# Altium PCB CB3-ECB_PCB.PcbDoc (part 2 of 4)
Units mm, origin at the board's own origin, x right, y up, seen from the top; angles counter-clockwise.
Board outline 195 x 139 mm, 4 copper layers (Top Layer, Layer 1, Layer 2, Bottom Layer), stack 1.56 mm thick; 363 components, 264 nets, 1430 pads, 630 vias.
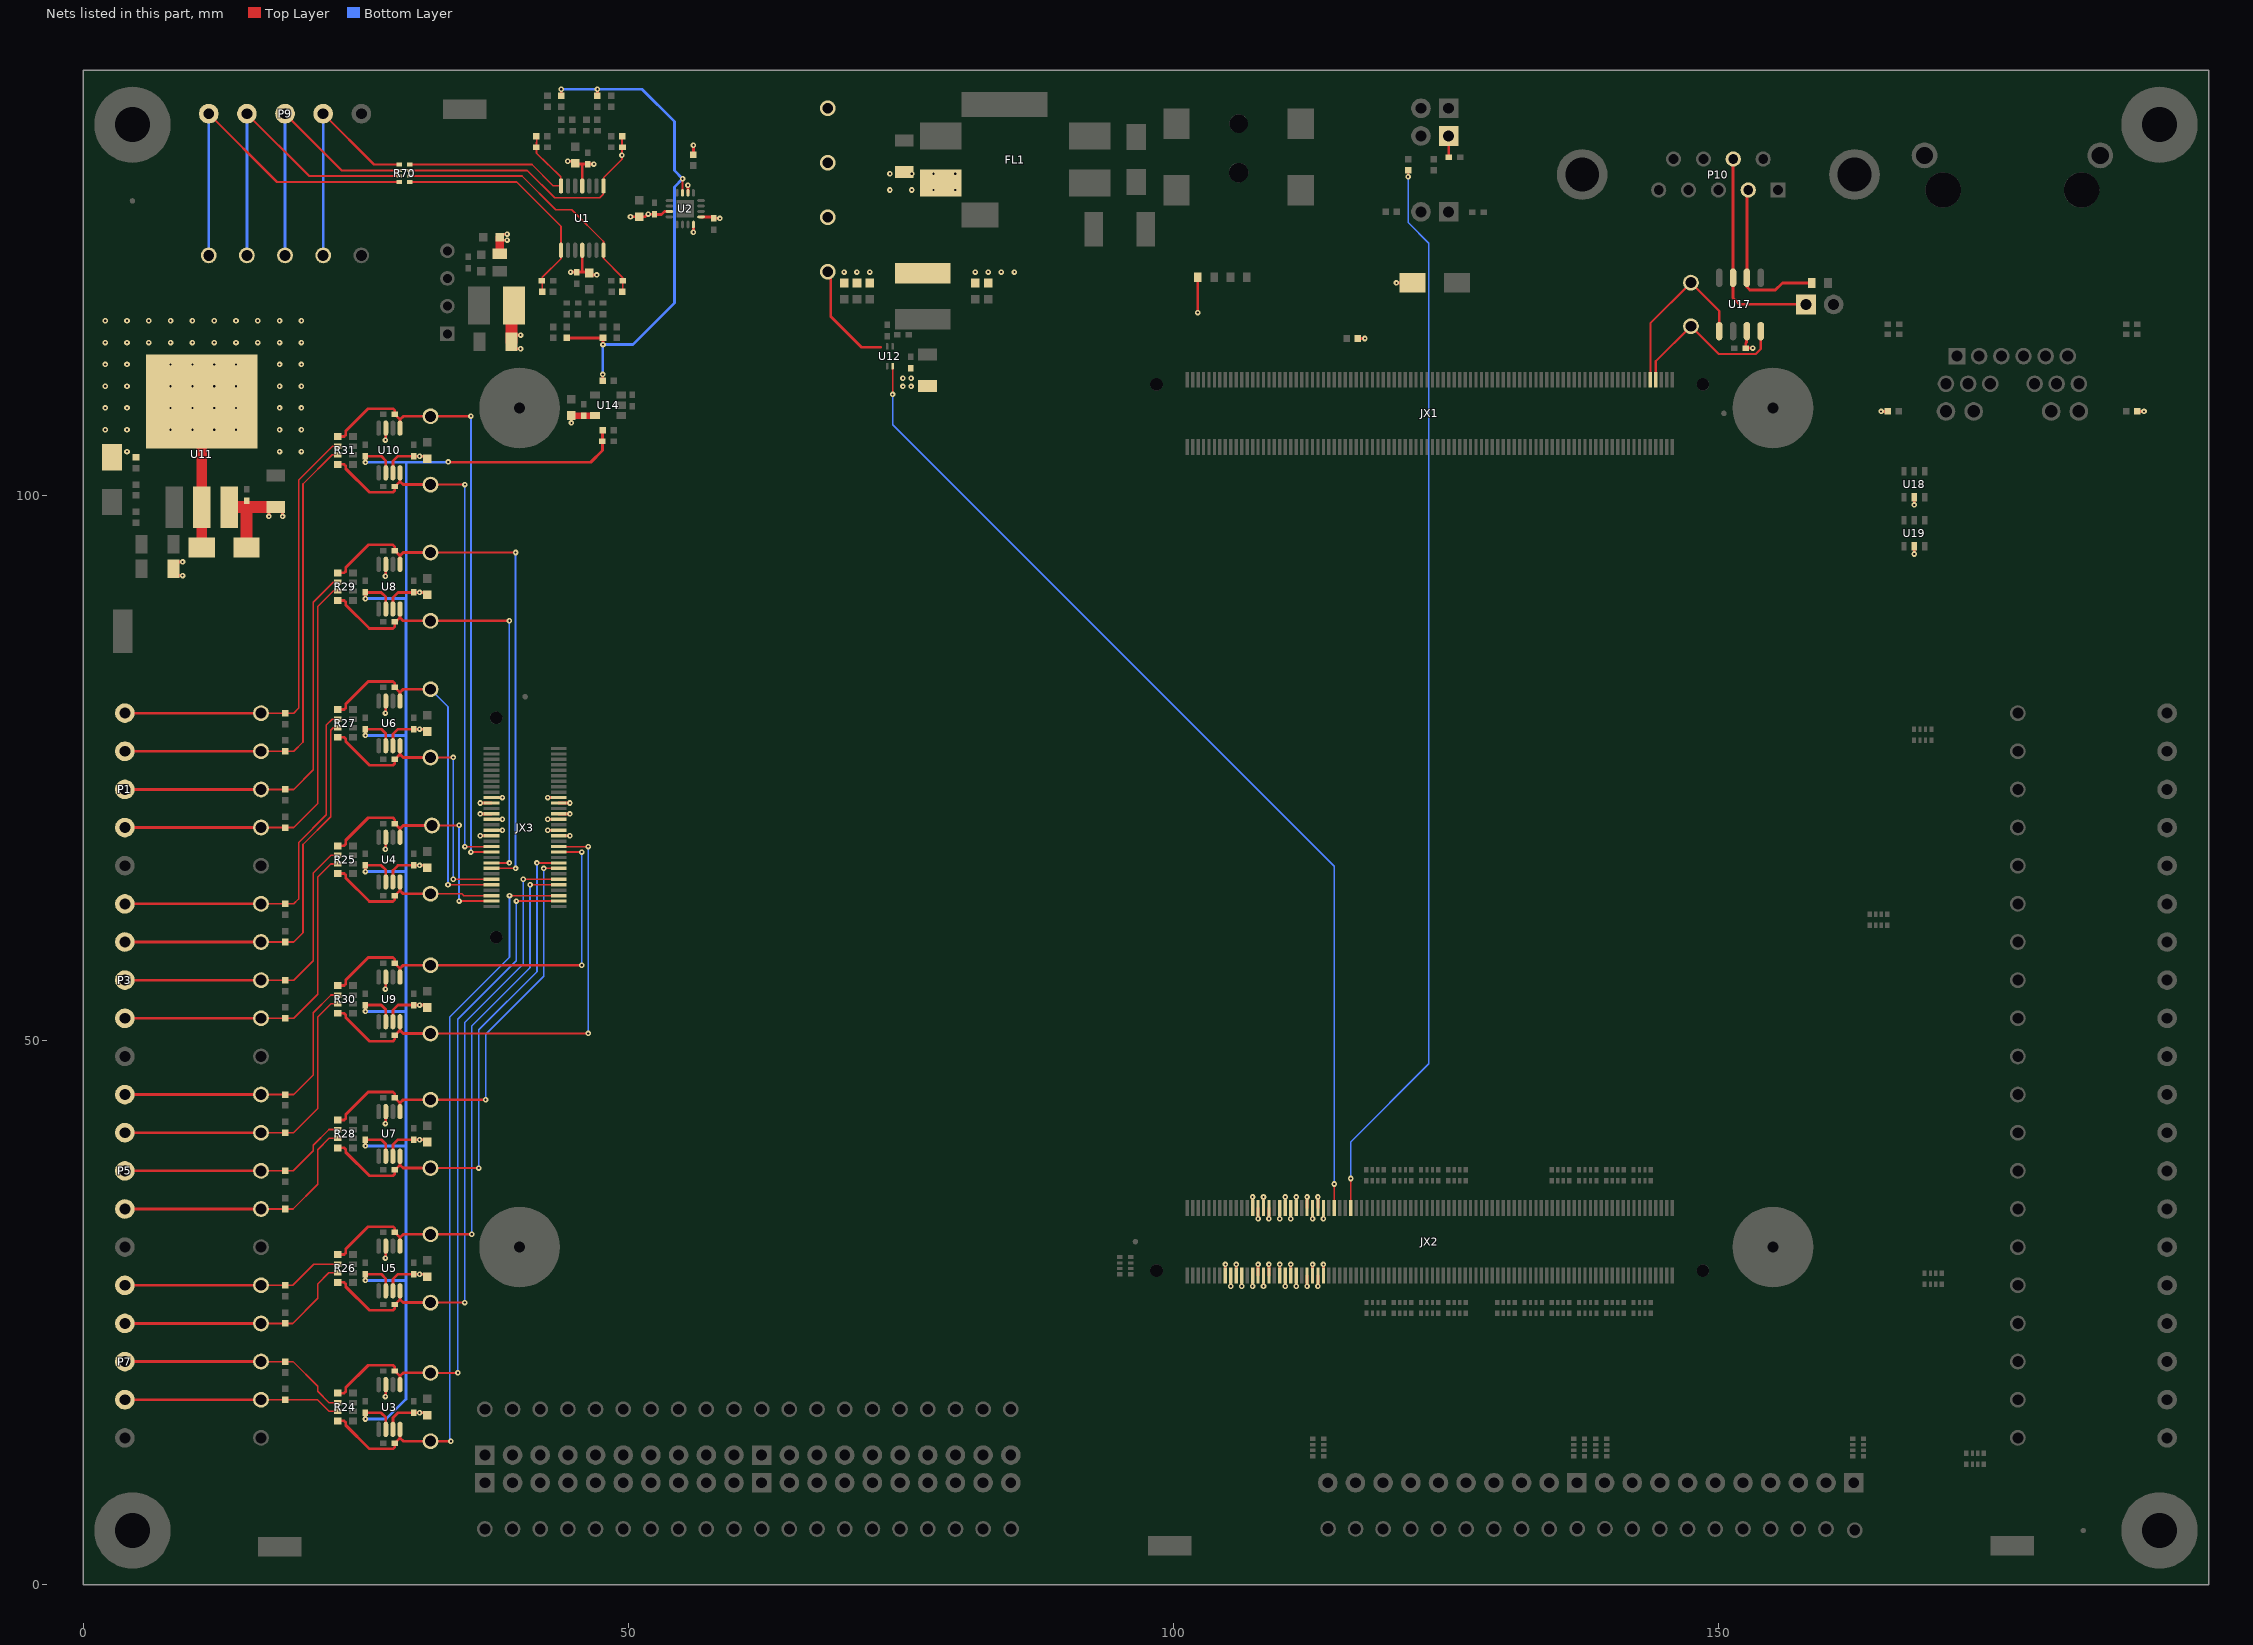
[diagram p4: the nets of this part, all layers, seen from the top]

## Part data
C1 C3 C9 C19 C22 C29 C32 C39 C42 C47 C52 C56 C64 C65 C69 C71 C79 C82 C83: library part CMP-055-000003-7, "CAP CER 10UF 10V X5R 0603 10% (Generic Imperix Component)", Case/Package=0603, Dielectric=X5R, Tolerance=10%, Voltage Rating (DC)=10V
C2 C4 C7 C8 C18 C21 C28 C31 C38 C41 C46 C51 C57 C58 C61 C67 C70 C73 C74 C75 C76 C77 C78 C84: library part CMP-004-000006-18, "CAP CER 100NF 25V X7R 0402 10% (Generic Imperix Component)", Case/Package=0402, Dielectric=X7R, Tolerance=10%, Voltage Rating (DC)=25V
C5 C10 C12 C14: library part CMP-027-000004-13, "CAP CER 56PF 50V C0G 0402 1% (Generic Imperix Component)", Case/Package=0402, Dielectric=C0G, Tolerance=1%, Voltage Rating (DC)=50V
C6 C11 C13 C15: library part CMP-012-000001-12, "CAP CER 10NF 25V X7R 0402 10% (Generic Imperix Component)", Case/Package=0402, Dielectric=X7R, Tolerance=10%, Voltage Rating (DC)=25V
C16 C17 C23 C24 C26 C27 C34 C35 C36 C37 C44 C45 C48 C49 C54 C55: library part CMP-004-000007-13, "CAP CER 12PF 50V C0G 0402 5% (Generic Imperix Component)", Case/Package=0402, Dielectric=C0G, Tolerance=5%, Voltage Rating (DC)=50V
C20 C25 C30 C33 C40 C43 C50 C53 C72 C80 C81: library part CMP-004-000008-13, "CAP CER 1UF 6.3V X5R 0402 5% (Generic Imperix Component)", Case/Package=0402, Dielectric=X5R, Tolerance=5%, Voltage Rating (DC)=6.3V
C59 C60 C62 C63 C66 C68: library part CMP-002-000022-5, "CAP CER 10UF 25V X5R 1206 10% (Generic Imperix Component)", Case/Package=1206, Dielectric=X5R, Tolerance=10%, Voltage Rating (DC)=25V
D1 D3 D4: library part CMP-005-000028-6, "Diode Schottky 40 V 3A Surface Mount SMA", Average Rectified Current=3A, Case/Package=DO-214AC, Forward Voltage=450mV, Max Forward Surge Current (Ifsm)=100A, Max Operating Temperature=150°C, Max Repetitive Reverse Voltage (Vrrm)=40V, Max Reverse Current=300uA, Min Operating Temperature=-55°C, Package Quantity=1
D2: library part CMP-030-000001-20, "32.5V Clamp 71A (8/20µs) Ipp Tvs Diode Surface Mount SMA (DO-214AC) Unidirectional", Breakdown Voltage=17.6V, Case/Package=DO-214AC, Clamping Voltage=32.5V, Leakage Current=200nA, Max Operating Temperature=150°C, Max Surge Current=1mA, Min Breakdown Voltage=16.7V, Min Operating Temperature=-55°C, Operating Supply Voltage=15V, Package Quantity=1, Peak Pulse Current=71A, Peak Pulse Power=400W, Power Line Protection=No
F1 F2 F3 F4 F5: library part CMP-031-000000-13, "Fiducial for pick&place (No BOM)"
F6: library part CMP-00170-3, "PTC Resettable Fuse 1.1A(hold)  1.95A(trip) 16VDC 1812", Case Code (Imperial)=1812, Case Code (Metric)=4532, Current Rating=100A, Hold Current=1.1A, Max Operating Temperature=85°C, Max Power Dissipation=800mW, Max Voltage Rating (DC)=16V, Min Operating Temperature=-40°C, Package Quantity=1500, Trip Current=1.95A
FL1: library part CMP-00068-6, "EMI Filter Block 15A 50VDC Flat Style SMD Automotive Embossed T/R"
J1 J2 J3 J4 J5: library part CMP-018-000000-12, "Natural PC Test Point Plating Surface Mount Mounting Type", Case/Package=1206, Color=Natural, Max Operating Temperature=125°C, Min Operating Temperature=-55°C, Package Quantity=2000
J6: library part CMP-056-000006-11, "2.0 x 6.5 mm, 5.0 A, Horizontal, Surface Mount (SMT), Dc Power Jack Connector", Body Color=Black, Flammability Rating="UL94 V-0", Max Operating Temperature=85°C, Min Operating Temperature=-25°C
JX1: library part CMP-070-000035-8, "JX1 for BBoard", Max Current Rating=1.25A, Max Operating Temperature=125°C, Max Voltage Rating (AC)=125V, Min Operating Temperature=-55°C
JX2: library part CMP-070-000034-11, "JX2 for BBoard", Max Current Rating=1.25A, Max Operating Temperature=125°C, Max Voltage Rating (AC)=125V, Min Operating Temperature=-55°C
JX3: library part CMP-070-000037-3, "JX3 for BBoard"
L1: library part CMP-259-000003-2, "Inductor Power Shielded Wirewound 3.3uH 30% 100KHz Ferrite 4.95A 0.0299Ohm DCR 2424 T/R", Case/Package=Nonstandard, Current Rating=4.95A, DC Resistance (DCR)=30mR, Inductance Tolerance=30%, Max Operating Temperature=105°C, Min Operating Temperature=-40°C, Saturation Current=6.5A, Test Frequency=100kHz
L3: library part CMP-007-000004-5, "Ferrite Beads Multi-Layer High Current 600Ohm 25% 100MHz 2A 100mOhm DCR 0805 T/R", Case Code (Imperial)=0805, Case Code (Metric)=2012, Current Rating=2A, DC Resistance (DCR)=100mR, Max Operating Temperature=125°C, Min Operating Temperature=-55°C, Package Quantity=4000, Self Resonant Frequency=100MHz, Tolerance=25%
L4: library part CMP-00092-4, "Inductor Power Wirewound 22uH 10% 0.6A 0.6Ohm DCR 1812", Case/Package=Nonstandard, DC Resistance (DCR)=600mR, Max DC Current=600mA, Max Operating Temperature=125°C, Min Operating Temperature=-40°C, Tolerance=10%
LED1: library part CMP-030-000000-10, "LED GREEN CLEAR 0603 SMD", Case Code (Imperial)=0603, Case Code (Metric)=1608, Color=Green, Forward Current=30mA, Forward Voltage=2.3V, Illumination Color=Green,Yellow, Lens Color=Colorless, Max Operating Temperature=85°C, Min Operating Temperature=-55°C, Package Quantity=3000, Power Dissipation=75mW, Reverse Voltage=5V, Test Current=5mA
P1 P2 P3 P4 P5 P6 P7 P8 P9: library part CMP-003-000046-13, "Conn PC Terminal Block 5 POS 3.5mm Solder Thru-Hole 17.5A", Color=Green, Current=10A, Current Rating=17.5A, Flammability Rating="UL94 V-0", Package Quantity=100, Voltage=300V, Voltage Rating=160V
P10: library part CMP-255-000000-9, "Conn D-Subminiature PIN 9 POS 2.74mm Solder RA Thru-Hole 9 Terminal 1 Port", Color=Black, Current Rating=5A, Manufacturer_Name="Amphenol Communications Solutions", Max Operating Temperature=105°C, Min Operating Temperature=-55°C, Voltage Rating=250V
P11 P14 P15 P16 P17 P18: library part CMP-003-000044-17, "Connector Header Through Hole 10 position 0.100\" (2.54mm)", Current Rating=3A, Flammability Rating="UL94 V-0", Insulation Color=Black, Max Operating Temperature=105°C, Min Operating Temperature=-40°C, Package Quantity=500, Voltage Rating=750V
P12 P13: library part CMP-003-000045-14, "Connector Header Through Hole 2 position 0.100\" (2.54mm)", Contact Resistance=25mR, Current=3A, Flammability Rating="UL94 V-0", Housing Color=Black, Insulation Resistance=10GR, Max Operating Temperature=105°C, Min Operating Temperature=-40°C, Package Quantity=1000, Voltage=50V, Voltage Rating (AC)=750V
P19: library part CMP-265-000000-4, "Conn Modular Jack RCP 12 POS 2.03mm Solder RA Thru-Hole 16 Terminal 1 Port Tray", Color=Green,Orange,Yellow, Max Operating Temperature=70°C, Min Operating Temperature=0°C
P20 P21: library part CMP-070-000025-6, "Connector Header Through Hole 2 position 0.100\" (2.54mm)", Contact Resistance=25mR, Current=3A, Flammability Rating="UL94 V-0", Housing Color=Black, Insulation Resistance=10GR, Max Operating Temperature=105°C, Min Operating Temperature=-40°C, Package Quantity=1000, Voltage=50V, Voltage Rating (AC)=750V
P22 P23 P24 P25: library part CMP-002-000068-13, "WA-SMSE SMT Steel Spacer, M3x5mm Thread External"
P26 P27 P28 P29: library part CMP-00128-10, "Hole and pad for spacer M3"
R2: library part CMP-00098-1, "RES SMD 1.8KΩ 1/8W 25PPM 0603 0.1% (Generic Imperix Component)", Case/Package=0603, Power Rating=1/8W, Temperature Coefficient=25ppm/°C, Tolerance=0.1%
R3 R4 R35 R37 R38 R39 R40 R71 R72 R73 R74 R75 R76 R77 R78 R79: library part CMP-00160-1, "RES SMD 1MΩ 1/16W 100PPM 0402 1% (Generic Imperix Component)", Case/Package=0402, Power Rating=1/16W, Temperature Coefficient=100ppm/°C, Tolerance=1%
R5 R8 R9 R11 R14 R16 R19 R20 R23 R41: library part CMP-009-000034-6, "RES SMD 6.19KΩ 1/16W 100PPM 0402 1% (Generic Imperix Component)", Case/Package=0402, Power Rating=1/16W, Temperature Coefficient=100ppm/°C, Tolerance=1%
R6 R7 R10 R12 R17 R18 R21 R22: library part CMP-00012-1, "RES SMD 3.09KΩ 1/16W 100PPM 0402 1% (Generic Imperix Component)", Case/Package=0402, Power Rating=1/16W, Temperature Coefficient=100ppm/°C, Tolerance=1%
R13 R15 R42 R46 R47 R48 R49 R50 R51 R52 R53 R58 R59 R60 R61 R62 R63 R64 R65 R70: library part CMP-009-000035-3, "Res Thick Film Array 33 Ohm 5% ±200ppm/°C ISOL 8-Pin 0804(4 X 0402) Convex SMD Automotive T/R", Case Code (Imperial)=0402, Case Code (Metric)=1005, Case/Package=0804, Max Operating Temperature=125°C, Min Operating Temperature=-55°C, Number of Resistors=4, Package Quantity=10000, Power Dissipation=63mW, Power Per Element=62.5mW, Resistance Tolerance=5%, Temperature Coefficient=200ppm/°C, Voltage Rating=50V, Voltage Rating (DC)=100V
R24 R25 R26 R27 R28 R29 R30 R31: library part CMP-017-000003-7, "10k Ohm ±0.1% 100mW Power Per Element Isolated 4 Resistor Network/Array ±25ppm/°C 1206 (3216 Metric), Convex, Long Side Terminals", Case Code (Imperial)=1206, Case Code (Metric)=3216, Max Operating Temperature=125°C, Min Operating Temperature=-55°C, Number of Resistors=4, Power Per Element=100mW, Temperature Coefficient=25ppm/°C, Tolerance=0.1%, Tolerance Relative=0.05%
R32 R82 R83: library part CMP-132-000003-2, "RES SMD 249Ω 1/16W 100PPM 0402 1% (Generic Imperix Component)", Case/Package=0402, Power Rating=1/16W, Temperature Coefficient=100ppm/°C, Tolerance=1%
R33 R84: library part CMP-150-000004-2, "RES SMD 777Ω 1/16W 25PPM 0402 0.1% (Generic Imperix Component)", Case/Package=0402, Power Rating=1/16W, Temperature Coefficient=25ppm/°C, Tolerance=0.1%
R34 R80: library part CMP-004-000018-3, "RES SMD 1.6Ω 1/16WW 200PPM 0402 5% (Generic Imperix Component)", Case/Package=0402, Power Rating=1/16W, Temperature Coefficient=200ppm/°C, Tolerance=5%
R36: library part CMP-006-000016-3, "RES SMD 120Ω 1/8W 50PPM 0603 1% (Generic Imperix Component)", Case/Package=0603, Power Rating=1/8W, Temperature Coefficient=50ppm/°C, Tolerance=1%
R43 R44: library part CMP-017-000008-4, "RES SMD 120Ω 1/16W 25PPM 0402 0.1% (Generic Imperix Component)", Case/Package=0402, Power Rating=1/16W, Temperature Coefficient=25ppm/°C, Tolerance=0.1%
R54 R55 R56 R57 R66 R67 R68 R69: library part CMP-062-000000-4, "Res Thick Film Array 10KΩ 5% ±200ppm/°C ISOL 8-Pin 0804(4 X 0402) Convex SMD Automotive T/R", Case Code (Imperial)=0402, Case Code (Metric)=1005, Case/Package=0804, Max Operating Temperature=125°C, Min Operating Temperature=-55°C, Number of Resistors=4, Package Quantity=1, Power Dissipation=63mW, Power Per Element=62.5mW, Resistance Tolerance=5%, Temperature Coefficient=200ppm/°C, Voltage Rating=50V, Voltage Rating (DC)=100V
R81: library part CMP-009-000006-6, "RES SMD 100KΩ 1/16W 100PPM 0402 1% (Generic Imperix Component)", Case/Package=0402, Power Rating=1/16W, Temperature Coefficient=100ppm/°C, Tolerance=1%
TP1 TP2 TP3 TP4 TP5 TP6 TP7 TP8 TP9 TP10 TP11 TP12 TP13 TP14 TP15 TP16 TP17 TP18 TP19 TP20 TP21 TP22 TP23 TP24 TP25 TP26 TP27 TP28 TP29 TP30 TP31 TP32 TP33 TP34 TP35 TP36 TP37 TP38 TP39 TP40 TP41 TP42 TP43 TP44 TP45 TP46 TP47 TP48 TP49 TP50 TP51 TP52 TP53 TP54 TP55 TP56 TP57 TP58 TP59 TP60 TP61 TP62 TP63 TP64 TP65 TP66 TP67 TP68 TP69 TP70 TP71 TP72 TP73 TP74 TP75 TP76 TP77 TP78 TP79 TP80 TP81 TP82 TP83 TP84 TP85 TP86 TP87 TP88 TP89 TP90 TP91 TP92 TP93 TP94 TP95 TP96 TP97 TP98 TP99 TP100 TP101 TP102 TP103 TP104 TP105 TP106 TP107 TP108 TP109 TP110 TP111 TP112 TP113 TP114 TP115 TP116 TP117 TP118 TP119 TP120 TP121 TP122 TP123 TP124 TP125 TP128 TP129: library part CMP-049-000000-14, "Black PC Test Point, Miniature Phosphor Bronze Silver Plating Through Hole Mounting Type", Color=Black, Package Quantity=100
U1: library part CMP-00166-1, "Precision Amplifiers Low-power low-noise four-channel precision amplifier with e-trim and super-beta inputs", Case/Package=TSSOP-14, Input Bias Current=100pA, Input Offset Voltage (Vos)=2uV, Max Operating Temperature=85°C, Min Operating Temperature=-40°C, Operating Supply Current=0.24mA
U2: library part CMP-029-000000-12, "DAC 4-CH Resistor-String 14-bit 16-Pin LFCSP EP T/R", Case/Package=QFN-16, Max Operating Temperature=105°C, Max Output Voltage=5.5V, Min Input Voltage=750mV, Min Operating Temperature=-40°C, Min Output Voltage=2.7V, Package Quantity=1500, Power Dissipation=7.15mW, Supply Current=1.1mA
U3 U4 U5 U6 U7 U8 U9 U10: library part CMP-011-000002-8, "Low Noise, Precision, 150MHz, Fully Differential Amplifier 8-TSOP -40 to 125", Case/Package=TSOP-8, Input Bias Current=1uA, Input Offset Voltage (Vos)=50uV, Max Operating Temperature=125°C, Min Operating Temperature=-40°C, Operating Supply Current=1.35mA
U11: library part CMP-011-000003-10, "IC REG LINEAR ADJ 1.5A DDPAK", Case/Package=TO263-3, Dropout Voltage=2V, Max Operating Temperature=125°C, Max Output current=1.5A, Max Output Voltage=37V, Max Supply Voltage=40V, Min Input Voltage=4.2V, Min Operating Temperature=0°C, Min Output Voltage=1.25V, Package Quantity=1, Power Supply Rejection Ratio (PSRR)=64dB, Quiescent Current=3.5mA, Reference Voltage=1.3V
U12: library part CMP-00162-5, "LMR436x0, 36-V, 1-A Buck Converter"
U13: library part CMP-004-000025-11, "Isolated Module DC DC Converter 1 Output 5V 200mA 10.8V - 13.2V Input", Isolation Voltage=1kV, Max Operating Temperature=85°C, Max Output current=200mA, Max Output Voltage=5V, Max Power Dissipation=1W, Max Supply Voltage=13.2V, Min Input Voltage=10.8V, Min Operating Temperature=-40°C
U14: library part CMP-00165-2, "Single Operational Amplifier, 50 µV Offset, 0.25 µV/°C, Zero-Drift Precision, Low Power", Case/Package=SOT-23-5, Input Bias Current=50pA, Input Offset Voltage (Vos)=14uV, Max Operating Temperature=125°C, Min Operating Temperature=-40°C, Operating Supply Current=21uA, Output Current per Channel=5mA
U17: library part CMP-00049-3, "Texas Instruments - SN65HVD232DR - Can Transceiver, 1MBPS, 1/1, 3.3V, SOIC-8, Full Reel", Case/Package=SOIC-8, Max Operating Temperature=85°C, Max Supply Voltage=3.6V, Min Operating Temperature=-40°C, Min Supply Voltage=3V, Package Quantity=2500, Supply Current=17mA
U18 U19: library part CMP-050-000000-12, "HDMIULC6 Series 4 Channel 6 V Bi-Directional ESD Protection - SOT-23-6", Breakdown Voltage=6V, Case/Package=SOT23-6, Clamping Voltage=17V, Leakage Current=500nA, Max Operating Temperature=125°C, Min Operating Temperature=-55°C, Operating Supply Voltage=5V, Package Quantity=1, Peak Pulse Current=5A, Power Line Protection=Yes, Test Current=1mA

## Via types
v1: diameter 0.508, hole 0.2, Top Layer to Bottom Layer, tented both sides, 435 vias
v2: diameter 0.508, hole 0.2, Top Layer to Bottom Layer, 194 vias
v3: diameter 0.66, hole 0.33, Top Layer to Bottom Layer, tented both sides, 1 vias

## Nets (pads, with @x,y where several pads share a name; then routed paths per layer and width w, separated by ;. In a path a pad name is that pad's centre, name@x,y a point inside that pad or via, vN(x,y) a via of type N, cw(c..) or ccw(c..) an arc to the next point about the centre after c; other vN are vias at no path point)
2V5REFBUF: C20.2 C25.2 C30.2 C33.2 C40.2 C43.2 C50.2 C53.2 C81.2 R80.2 U3.2 U4.2 U5.2 U6.2 U7.2 U8.2 U9.2 U10.2 | length 166.7
  Top Layer w0.254: v1(25.875,15.23) C20.2@25.875,15.806 27.324,15.806 27.747,15.383 U3.2@27.747,14.282 ; v1(25.875,27.943) C30.2@25.875,28.519 27.324,28.519 27.747,28.096 U5.2@27.747,26.994 ; v1(25.875,40.287) C40.2@25.875,40.864 27.324,40.863 27.747,40.44 U7.2@27.747,39.339 ; v1(25.875,52.632) C50.2@25.875,53.208 27.324,53.208 27.747,52.784 U9.2@27.747,51.683 ; v1(25.875,65.459) C25.2@25.875,66.035 27.324,66.035 27.747,65.611 U4.2@27.747,64.51 ; v1(25.875,77.956) C33.2@25.875,78.532 27.324,78.532 27.747,78.108 U6.2@27.747,77.007 ; v1(25.875,90.503) C43.2@25.875,91.079 27.324,91.079 27.747,90.656 U8.2@27.747,89.554 ; v1(25.875,103) C53.2@25.875,103.576 27.324,103.576 27.747,103.153 U10.2@27.747,102.051 ; v2(33.475,103.05) 33.5,103.025 46.55,103.025 47.625,104.1 C81.2@47.625,104.95 47.625,105.95 R80.2@47.65,105.975
  Bottom Layer w0.254: v1(25.875,15.23) 27.78,15.23 29.6,17.05 29.6,27.943 ; v1(25.875,27.943) 29.6,27.943 29.6,40.287 ; v1(25.875,40.287) 29.6,40.287 ; v1(25.875,52.632) 29.6,52.632 ; v1(25.875,65.459) 29.6,65.459 ; v1(25.875,77.956) 29.6,77.956 ; v1(25.875,103) 25.9,103.025 29.675,103.025 ; v1@25.9,90.528 29.625,90.528 ; v2(33.475,103.05) 33.45,103.025 29.675,103.025 ; 29.6,40.287 29.6,52.632 ; 29.6,52.632 29.6,65.459 ; 29.6,65.459 29.6,77.956 ; 29.6,77.956 29.6,90.503 29.625,90.528 ; 29.625,90.528 29.625,102.975 29.675,103.025
2V5REFOUT: R7.2 R12.2 R18.2 R22.2 R81.1 U2.15 | length 46.8
  Top Layer w0.152: U2.15@54.974,127.735 U2.15@54.972,127.734 54.972,129.035 v1(54.975,129.037)
  Top Layer w0.254: R22.2@43.852,136.633 v1(43.852,137.251) ; R7.2@44.366,114.432 R12.2@47.676,114.432 v1(47.676,113.814) ; R18.2@47.162,136.633 v1(47.162,137.251) ; R81.1@47.65,110.5 v1(47.65,111.075)
  Bottom Layer w0.254: v1(43.852,137.251) v1(47.162,137.251) 47.26,137.251 51.249,137.251 54.225,134.275 54.225,129.788 v1(54.975,129.037) 54.225,128.287 54.225,117.625 50.414,113.814 v1(47.676,113.814) 47.663,113.801 47.663,111.088 v1(47.65,111.075)
3V3: C7.2 C56.2 C69.2 C70.2 C71.2 C78.2 C82.2 C83.2 D4.K L1.2 P12.1 R11.2 R41.1 R82.2 R83.2 TP122.1 U2.8 U2.9 U2.14 U12.8 U17.3 U18.5 U19.5 | length 23.3
  Top Layer w0.25: v1(55.974,124.128) U2.8@55.974,124.832 ; U2.9@56.672,125.532 57.705,125.532 57.828,125.409 C7.2@57.828,125.396 57.83,125.398 58.398,125.398 v1(58.4,125.4) ; C70.2@152.525,113.5 v2(153.175,113.5) ; v2(164.95,107.68) R83.2@165.575,107.68 ; R82.2@188.525,107.68 v2(189.075,107.68) v2@189.125,107.68
  Top Layer w0.254: U2.14@55.471,127.736 v1(55.471,128.44) ; R11.2@55.972,131.5 v1(55.972,132.1) ; TP122.1@68.3,121.092 68.571,120.821 68.571,116.384 71.38,113.575 U12.8@73.087,113.575 73.142,113.575 ; R41.1@116.95,114.375 v1@117.583,114.375 ; v1(120.475,119.475) D4.K@121.95,119.475 ; P12.1@125.27,132.96 125.27,131.005 C78.2@125.275,131 ; C70.2@152.525,113.5 152.525,113.925 152.6,114 152.6,115.015 U17.3@152.635,115.05 ; v1(168,94.6) U19.5@168,95.3 ; v1(168,99.1) U18.5@168,99.8
  other v1: 117.586,114.375
  other v2: 69.8,120.475 70.975,120.475 72.15,120.475 81.825,120.475 83.025,120.475 84.225,120.475 85.425,120.475
5V2: C1.2 C2.2 C8.2 C9.2 C18.2 C19.2 C21.2 C22.2 C28.2 C29.2 C31.2 C32.2 C38.2 C39.2 C41.2 C42.2 C46.2 C47.2 C51.2 C52.2 C63.2 C77.2 C79.2 D1.A D3.K JX3.10 JX3.11 JX3.13 JX3.14 JX3.16 JX3.17 JX3.44 JX3.45 JX3.47 JX3.48 JX3.50 JX3.51 R32.2 TP123.1 U1.4 U2.3 U3.3 U3.7 U4.3 U4.7 U5.3 U5.7 U6.3 U6.7 U7.3 U7.7 U8.3 U8.7 U9.3 U9.7 U10.3 U10.7 U11.2 U14.5 | length 79
  Top Layer w0.25: C63.2@8.675,92.625 v2(9.1,92.625) ; C63.2@8.675,93.875 v2(9.1,93.875) ; v1(44.7,120.467) C2.2@45.272,120.467 ; v2(44.775,106.625) C79.2@44.775,107.3 ; C1.2@46.417,120.389 46.495,120.467 46.495,120.403 46.692,120.205 v1(47.1,120.205) ; v1(50.2,125.55) C9.2@51,125.55 51.52,125.55 51.759,125.789 v1(51.828,125.789) 51.835,125.782 52.393,125.782 C8.2@52.4,125.775 ; C8.2@52.4,125.8 C8.2@52.4,125.775 ; U2.3@53.772,126.034 53.324,126.034 53.04,125.75 52.425,125.75 C8.2@52.4,125.775
  Top Layer w0.254: v1@27.747,17.314 U3.7@27.747,18.381 ; v1@27.747,30.026 U5.7@27.747,31.094 ; v1@27.747,42.371 U7.7@27.747,43.439 ; v1@27.747,54.715 U9.7@27.747,55.783 ; v1@27.747,67.542 U4.7@27.747,68.61 ; v1@27.747,80.039 U6.7@27.747,81.107 ; v1@27.747,92.586 U8.7@27.747,93.654 ; v1@27.747,105.083 U10.7@27.747,106.151 ; U3.3@28.397,14.282 28.397,15.349 28.854,15.806 C18.2@30.305,15.806 v1(30.85,15.805) ; U5.3@28.397,26.994 28.397,28.062 28.854,28.519 C21.2@30.305,28.519 ; U7.3@28.397,39.339 28.397,40.407 28.854,40.864 C28.2@30.305,40.864 ; U9.3@28.397,51.683 28.397,52.751 28.854,53.208 C31.2@30.305,53.208 ; U4.3@28.397,64.51 28.397,65.578 28.854,66.035 C38.2@30.305,66.035 ; U6.3@28.397,77.007 28.397,78.075 28.854,78.532 C41.2@30.305,78.532 ; U8.3@28.397,89.554 28.397,90.622 28.854,91.079 C46.2@30.305,91.079 ; U10.3@28.397,102.051 28.397,103.119 28.854,103.576 C51.2@30.305,103.576 ; C21.2@30.306,28.519 v1(30.85,28.518) ; C28.2@30.306,40.863 v1(30.85,40.862) ; C31.2@30.306,53.207 v1(30.85,53.207) ; C38.2@30.306,66.034 v1(30.85,66.034) ; C41.2@30.306,78.531 v1(30.85,78.531) ; C46.2@30.306,91.079 v1(30.85,91.078) ; C51.2@30.306,103.576 v1(30.85,103.575) ; v1(30.85,103.575) 30.851,103.576 C52.2@31.223,103.576 ; v1@30.851,15.806 C19.2@31.223,15.806 ; v1@30.851,28.519 C22.2@31.223,28.519 ; v1@30.851,40.864 C29.2@31.223,40.864 ; v1@30.851,53.208 C32.2@31.223,53.208 ; v1@30.851,66.035 C39.2@31.223,66.035 ; v1@30.851,78.532 C42.2@31.223,78.532 ; v1@30.851,91.079 C47.2@31.223,91.079 ; v1(36.421,68.755) JX3.44@37.435,68.755 ; v1(36.421,70.755) JX3.48@37.435,70.755 ; v1(36.421,71.755) JX3.50@37.435,71.755 ; JX3.45@37.435,69.255 v1(38.45,69.255) ; JX3.47@37.435,70.255 v1(38.45,70.255) ; JX3.51@37.435,72.255 v1(38.45,72.255) ; v1(42.611,69.255) JX3.16@43.625,69.255 ; v1(42.611,70.255) JX3.14@43.625,70.255 ; v1(42.611,72.255) JX3.10@43.625,72.255 ; JX3.17@43.625,68.755 v1(44.64,68.755) ; JX3.13@43.625,70.755 v1(44.64,70.755) ; JX3.11@43.625,71.755 v1(44.64,71.755) ; C2.2@45.272,120.467 45.771,120.467 ; U1.4@45.771,122.476 45.771,120.467 ; C1.2@46.495,120.467 45.771,120.467
  Top Layer w0.6: C79.2@44.775,107.3 C77.2@45.925,107.3 U14.5@46.95,107.3
  Top Layer w1: D1.A@10.825,95.165 D1.A@10.86,95.2 U11.2@10.86,98.9 U11.2@10.86,108.6
  other v1: 27.715,17.281 27.715,29.994 27.715,42.339 27.715,54.683 27.715,67.51 27.715,80.007 27.715,92.554 27.715,105.051
  other v2: 4,104 18,104 20,104 2,106 4,106 8,106 10,106 12,106 14,106 18,106 20,106 2,108 4,108 8,108 10,108 12,108 14,108 18,108 20,108 2,110 4,110 8,110 10,110 12,110 14,110 18,110 20,110 2,112 4,112 8,112 10,112 12,112 14,112 18,112 20,112 2,114 4,114 6,114 8,114 10,114 12,114 14,114 16,114 18,114 20,114 2,116 4,116 6,116 8,116 10,116 12,116 14,116 16,116 18,116 20,116
+12V: C57.2 C59.2 C60.2 C61.2 C66.2 C68.2 D1.K FL1.2 JX2.13 JX2.14 JX2.15 JX2.16 JX2.18 JX2.19 JX2.20 JX2.21 JX2.23 JX2.24 JX2.25 JX2.26 JX2.155 JX2.156 JX2.157 JX2.158 JX2.160 JX2.161 JX2.162 JX2.163 JX2.165 JX2.166 JX2.167 JX2.168 JX2.170 JX2.171 JX2.172 JX2.173 L4.1 R2.2 TP124.1 U11.3 U12.4 | length 44.4
  Top Layer w0.25: v2(17.025,98.05) C60.2@17.025,98.475 ; v2(18.275,98.05) C60.2@18.275,98.475 ; C66.2@39.683,113.437 v2(40.108,113.437) ; C66.2@39.683,114.687 v2(40.108,114.687) ; v2(102.25,116.75) R2.2@102.25,120
  Top Layer w0.254: JX2.173@104.78,28.41 v1(104.78,29.411) ; v1(105.28,27.409) JX2.172@105.28,28.41 ; JX2.171@105.78,28.41 v1(105.78,29.411) ; v1(106.28,27.409) JX2.170@106.28,28.41 ; v1(107.28,27.409) JX2.168@107.28,28.41 ; JX2.13@107.28,34.6 v1(107.28,35.601) ; JX2.167@107.78,28.41 v1(107.78,29.411) ; v1(107.78,33.599) JX2.14@107.78,34.6 ; v1(108.28,27.409) JX2.166@108.28,28.41 ; JX2.15@108.28,34.6 v1(108.28,35.601) ; JX2.165@108.78,28.41 v1(108.78,29.411) ; v1(108.78,33.599) JX2.16@108.78,34.6 ; JX2.163@109.78,28.41 v1(109.78,29.411) ; v1(109.78,33.599) JX2.18@109.78,34.6 ; v1(110.28,27.409) JX2.162@110.28,28.41 ; JX2.19@110.28,34.6 v1(110.28,35.601) ; JX2.161@110.78,28.41 v1(110.78,29.411) ; v1(110.78,33.599) JX2.20@110.78,34.6 ; v1(111.28,27.409) JX2.160@111.28,28.41 ; JX2.21@111.28,34.6 v1(111.28,35.601) ; v1(112.28,27.409) JX2.158@112.28,28.41 ; JX2.23@112.28,34.6 v1(112.28,35.601) ; JX2.157@112.78,28.41 v1(112.78,29.411) ; v1(112.78,33.599) JX2.24@112.78,34.6 ; v1(113.28,27.409) JX2.156@113.28,28.41 ; JX2.25@113.28,34.6 v1(113.28,35.601) ; JX2.155@113.78,28.41 v1(113.78,29.411) ; v1(113.78,33.599) JX2.26@113.78,34.6
  Top Layer w1.1: U11.3@13.4,98.9 14.96,98.9 ; D1.K@14.96,95.2 14.96,98.9 ; C60.2@17.65,98.9 14.96,98.9 ; C66.2@39.258,114.062 39.258,115.558 39.3,115.6 39.3,117.2 L4.1@39.5,117.4
  other v2: 75.2,109.975 75.95,109.975 75.2,110.725 75.95,110.725 74,128 76,128 78,128 80,128 74,129.5 76,129.5 78,129.5 80,129.5
-5V: C3.1 C4.1 C65.1 L3.2 TP125.1 U1.11 | length 6.6
  Top Layer w0.25: C65.1@38.425,123.4 v2(38.875,123.4) ; C65.1@38.425,123.95 v2(38.875,123.95) ; v1(44.443,130.647) C3.1@44.851,130.647 ; C4.1@46.27,130.385 v1(46.843,130.385)
  Top Layer w0.254: C3.1@45.048,130.385 45.771,130.385 ; U1.11@45.771,128.376 45.771,130.385 ; C4.1@46.27,130.385 45.771,130.385
  Top Layer w0.8: L3.2@38.2,122.15 C65.1@38.2,123.675
ADC0_N: P7.2 R24.3 R76.2 TP88.1 | length 20
  Top Layer w0.152: TP88.1@16.3,17 R76.2@18.5,17 21.472,17 22.541,15.931 R24.3@23.341,15.931
  Top Layer w0.25: P7.2@3.8,17 TP88.1@16.3,17
ADC0_P: P7.3 R24.2 R77.2 TP96.1 | length 21.4
  Top Layer w0.152: TP96.1@16.3,20.5 R77.2@18.5,20.5 19.225,20.5 21.5,18.225 21.5,17.772 22.541,16.731 R24.2@23.341,16.731
  Top Layer w0.25: P7.3@3.8,20.5 TP96.1@16.3,20.5
ADC1_N: P7.4 R26.3 R72.2 TP64.1 | length 22.2
  Top Layer w0.152: TP64.1@16.3,24 R72.2@18.5,24 19.2,24 21.5,26.3 21.5,27.625 22.519,28.644 R26.3@23.341,28.644
  Top Layer w0.25: P7.4@3.8,24 TP64.1@16.3,24
ADC1_P: P7.5 R26.2 R73.2 TP80.1 | length 20.3
  Top Layer w0.152: TP80.1@16.3,27.5 R73.2@18.5,27.5 19.2,27.5 21.144,29.444 R26.2@23.341,29.444
  Top Layer w0.25: P7.5@3.8,27.5 TP80.1@16.3,27.5
ADC2_N: P5.2 R28.3 R38.2 TP87.1 | length 24.1
  Top Layer w0.152: TP87.1@16.3,34.5 R38.2@18.5,34.5 19.225,34.5 21.5,36.775 21.5,39.948 22.541,40.989 R28.3@23.341,40.989
  Top Layer w0.25: P5.2@3.8,34.5 TP87.1@16.3,34.5
ADC2_P: P5.3 R28.2 R39.2 TP95.1 | length 21.4
  Top Layer w0.152: TP95.1@16.3,38 R39.2@18.5,38 19.25,38 21.094,39.844 21.094,40.341 22.541,41.789 R28.2@23.341,41.789
  Top Layer w0.25: P5.3@3.8,38 TP95.1@16.3,38
ADC3_N: P5.4 R3.2 R30.3 TP63.1 | length 29.4
  Top Layer w0.152: TP63.1@16.3,41.5 R3.2@18.5,41.5 19.275,41.5 21.5,43.725 21.5,52.113 22.72,53.333 R30.3@23.341,53.333
  Top Layer w0.25: P5.4@3.8,41.5 TP63.1@16.3,41.5
ADC3_P: P5.5 R4.2 R30.2 TP79.1 | length 26.7
  Top Layer w0.152: TP79.1@16.3,45 R4.2@18.5,45 19.3,45 21.094,46.794 21.094,52.507 22.72,54.133 R30.2@23.341,54.133
  Top Layer w0.25: P5.5@3.8,45 TP79.1@16.3,45
ADC4_N: P3.2 R25.3 R78.2 TP86.1 | length 31.7
  Top Layer w0.152: TP86.1@16.3,52 R78.2@18.5,52 19.3,52 21.5,54.2 21.5,64.96 22.7,66.16 R25.3@23.341,66.16
  Top Layer w0.25: P3.2@3.8,52 TP86.1@16.3,52
ADC4_P: P3.3 R25.2 R79.2 TP94.1 | length 29
  Top Layer w0.152: TP94.1@16.3,55.5 R79.2@18.5,55.5 19.3,55.5 21.094,57.294 21.094,65.334 22.72,66.96 R25.2@23.341,66.96
  Top Layer w0.25: P3.3@3.8,55.5 TP94.1@16.3,55.5
ADC5_N: P3.4 R27.3 R74.2 TP62.1 | length 37.1
  Top Layer w0.152: TP62.1@16.3,59 R74.2@18.5,59 19.3,59 20.15,59.85 20.15,67.949 22.7,70.499 22.7,78.425 22.932,78.657 R27.3@23.341,78.657
  Top Layer w0.25: P3.4@3.8,59 TP62.1@16.3,59
ADC5_P: P3.5 R27.2 R75.2 TP78.1 | length 34.4
  Top Layer w0.152: TP78.1@16.3,62.5 R75.2@18.5,62.5 19.3,62.5 19.744,62.944 19.744,68.117 22.294,70.667 22.294,78.919 22.825,79.45 23.334,79.45 R27.2@23.341,79.457
  Top Layer w0.25: P3.5@3.8,62.5 TP78.1@16.3,62.5
ADC6_N: P1.2 R29.3 R40.2 TP85.1 | length 39.1
  Top Layer w0.152: TP85.1@16.3,69.5 R40.2@18.5,69.5 19.3,69.5 21.5,71.7 21.5,89.789 22.915,91.204 R29.3@23.341,91.204
  Top Layer w0.25: P1.2@3.8,69.5 TP85.1@16.3,69.5
ADC6_P: P1.3 R29.2 R71.2 TP93.1 | length 36.4
  Top Layer w0.152: TP93.1@16.3,73 R71.2@18.5,73 19.3,73 21.094,74.794 21.094,90.183 22.915,92.004 R29.2@23.341,92.004
  Top Layer w0.25: P1.3@3.8,73 TP93.1@16.3,73
ADC7_N: P1.4 R31.3 R35.2 TP61.1 | length 44.7
  Top Layer w0.152: TP61.1@16.3,76.5 R35.2@18.5,76.5 19.3,76.5 20.15,77.35 20.15,101.025 22.826,103.701 R31.3@23.341,103.701
  Top Layer w0.25: P1.4@3.8,76.5 TP61.1@16.3,76.5
ADC7_P: P1.5 R31.2 R37.2 TP77.1 | length 41.9
  Top Layer w0.152: TP77.1@16.3,80 R37.2@18.5,80 19.3,80 19.744,80.444 19.744,101.369 22.852,104.477 23.316,104.477 R31.2@23.341,104.501
  Top Layer w0.25: P1.5@3.8,80 TP77.1@16.3,80
AIN0_N: C16.2 JX3.29 R24.1 TP106.1 U3.5 | length 63.2
  Top Layer w0.152: v1(39.725,62.755) JX3.29@43.625,62.755
  Top Layer w0.203: TP106.1@31.852,19.465 v1@34.357,19.465
  Top Layer w0.254: R24.1@23.341,17.601 23.926,17.601 24.075,17.75 24.075,18.105 26.138,20.168 28.39,20.168 28.574,19.983 C16.2@28.574,19.638 29.047,19.166 ; U3.5@29.047,18.381 29.047,19.166 ; TP106.1@31.852,19.465 29.347,19.465 29.047,19.166
  Bottom Layer w0.152: v1(34.357,19.479) 34.357,51.92 39.725,57.288 v1(39.725,62.755)
AIN0_P: C23.2 JX3.28 R24.4 TP108.1 U3.4 | length 70
  Top Layer w0.152: v1@39.091,63.255 v1(39.095,63.255) JX3.28@43.625,63.255
  Top Layer w0.203: TP108.1@31.852,13.198 v1(33.719,13.198)
  Top Layer w0.254: R24.4@23.341,15.061 23.926,15.061 24.075,14.913 24.075,14.655 26.235,12.495 28.389,12.495 28.574,12.68 28.574,12.925 28.574,13.024 29.047,13.497 ; U3.4@29.047,14.282 29.047,13.497 ; TP108.1@31.852,13.198 29.347,13.198 29.047,13.497
  Bottom Layer w0.152: v1@33.617,13.198 33.651,13.232 33.651,13.431 33.617,13.465 33.617,52.12 39.095,57.598 v1(39.095,63.255)
AIN1_N: C26.2 JX3.26 R26.1 TP110.1 U5.5 | length 52
  Top Layer w0.152: v1(40.985,64.255) JX3.26@43.625,64.255
  Top Layer w0.203: TP110.1@31.852,32.178 v1@35.56,32.178
  Top Layer w0.254: R26.1@23.341,30.314 23.926,30.314 24.075,30.463 24.075,30.818 26.138,32.881 28.39,32.881 28.575,32.696 C26.2@28.574,32.351 29.048,31.878 ; U5.5@29.047,31.094 29.048,31.878 ; TP110.1@31.852,32.178 29.347,32.178 29.048,31.878
  Bottom Layer w0.152: v1(35.631,32.178) 35.631,51.29 40.985,56.643 v1(40.985,64.255)
AIN1_P: C34.2 JX3.25 R26.4 TP112.1 U5.4 | length 58.7
  Top Layer w0.152: v1(40.355,64.755) JX3.25@43.625,64.755
  Top Layer w0.203: TP112.1@31.852,25.91 v1@35.001,25.91
  Top Layer w0.254: R26.4@23.341,27.774 23.926,27.774 24.075,27.625 24.075,27.368 26.235,25.208 28.39,25.208 28.574,25.392 C34.2@28.574,25.737 29.047,26.21 ; U5.4@29.047,26.994 29.047,26.21 ; TP112.1@31.852,25.91 29.347,25.91 29.047,26.21
  Bottom Layer w0.152: v1(34.994,25.91) 34.994,51.447 34.994,51.618 40.355,56.978 v1(40.355,64.755)
AIN2_N: C36.2 JX3.23 R28.1 TP114.1 U7.5 | length 41.2
  Top Layer w0.152: v1(42.24,65.755) JX3.23@43.625,65.755
  Top Layer w0.203: TP114.1@31.852,44.522 v1(36.906,44.522)
  Top Layer w0.254: R28.1@23.341,42.659 23.926,42.659 24.075,42.807 24.075,43.163 26.138,45.225 28.39,45.225 28.575,45.04 C36.2@28.574,44.695 29.048,44.223 ; U7.5@29.047,43.439 29.048,44.223 ; TP114.1@31.852,44.522 29.347,44.522 29.048,44.223
  Bottom Layer w0.152: v1(36.906,44.522) 36.906,50.533 42.245,55.871 v1@42.245,65.755
AIN2_P: C44.2 JX3.22 R28.4 TP116.1 U7.4 | length 47.9
  Top Layer w0.152: v1(41.615,66.255) JX3.22@43.625,66.255
  Top Layer w0.203: TP116.1@31.852,38.255 v1(36.269,38.255)
  Top Layer w0.254: R28.4@23.341,40.119 23.926,40.119 24.075,39.97 24.075,39.712 26.235,37.552 28.39,37.552 28.574,37.737 28.574,37.982 28.574,38.081 29.047,38.554 ; U7.4@29.047,39.339 29.047,38.554 ; TP116.1@31.852,38.255 29.347,38.255 29.047,38.554
  Bottom Layer w0.152: v1(36.269,38.255) 36.269,50.937 41.615,56.282 v1(41.615,66.255)
AIN3_N: C48.2 JX3.20 R30.1 TP118.1 U9.5 | length 37.6
  Top Layer w0.152: JX3.20@43.625,67.255 v1@45.72,67.255
  Top Layer w0.203: TP118.1@31.852,56.867 v1(45.72,56.867)
  Top Layer w0.254: R30.1@23.341,55.003 23.926,55.003 24.075,55.152 24.075,55.507 26.138,57.57 28.39,57.57 28.575,57.385 C48.2@28.574,57.04 29.048,56.567 ; U9.5@29.047,55.783 29.048,56.567 ; TP118.1@31.852,56.867 29.347,56.867 29.048,56.567
  Bottom Layer w0.152: v1(45.72,56.867) v1(45.72,67.246)
AIN3_P: C54.2 JX3.19 R30.4 TP120.1 U9.4 | length 45.6
  Top Layer w0.152: JX3.19@43.625,67.755 v1(46.33,67.755)
  Top Layer w0.203: TP120.1@31.852,50.599 v1@46.33,50.599
  Top Layer w0.254: R30.4@23.341,52.463 23.926,52.463 24.075,52.314 24.075,52.057 26.235,49.896 28.39,49.896 28.574,50.081 C54.2@28.574,50.426 29.047,50.899 ; U9.4@29.047,51.683 29.047,50.899 ; TP120.1@31.852,50.599 29.347,50.599 29.047,50.899
  Bottom Layer w0.152: v1(46.33,50.609) v1(46.33,67.755)
AIN4_N: C17.2 JX3.32 R25.1 TP107.1 U4.5 | length 23.8
  Top Layer w0.152: v1(34.468,62.755) JX3.32@37.435,62.755
  Top Layer w0.203: TP107.1@31.852,69.694 v1@34.468,69.694
  Top Layer w0.254: R25.1@23.341,67.83 23.926,67.83 24.075,67.979 24.075,68.334 26.138,70.397 28.39,70.397 28.575,70.212 C17.2@28.574,69.867 29.048,69.394 ; U4.5@29.047,68.61 29.048,69.394 ; TP107.1@31.853,69.694 29.347,69.694 29.048,69.394
  Bottom Layer w0.152: v1(34.468,62.755) v1(34.468,69.71)
AIN4_P: C24.2 JX3.33 R25.4 TP109.1 U4.4 | length 16.9
  Top Layer w0.152: TP109.1@31.852,63.426 34.731,63.426 34.903,63.255 JX3.33@37.435,63.255
  Top Layer w0.254: R25.4@23.341,65.29 23.926,65.29 24.075,65.141 24.075,64.884 26.235,62.723 28.39,62.723 28.574,62.908 C24.2@28.574,63.253 29.047,63.726 ; U4.4@29.047,64.51 29.047,63.726 ; TP109.1@31.852,63.426 29.347,63.426 29.047,63.726
AIN5_N: C27.2 JX3.35 R27.1 TP111.1 U6.5 | length 33.9
  Top Layer w0.152: v1@33.477,64.255 JX3.35@37.435,64.255
  Top Layer w0.254: R27.1@23.341,80.327 23.926,80.327 24.075,80.476 24.075,80.831 26.138,82.893 28.39,82.893 28.575,82.709 C27.2@28.574,82.364 29.048,81.891 ; U6.5@29.047,81.107 29.048,81.891 ; TP111.1@31.852,82.191 29.347,82.191 29.048,81.891
  Bottom Layer w0.152: TP111.1@31.852,82.191 33.452,80.591 v1(33.452,64.255)
AIN5_P: C35.2 JX3.36 R27.4 TP113.1 U6.4 | length 28
  Top Layer w0.152: v1(33.934,64.755) JX3.36@37.435,64.755
  Top Layer w0.203: TP113.1@31.852,75.923 v1@33.934,75.923
  Top Layer w0.254: R27.4@23.341,77.787 23.926,77.787 24.075,77.638 24.075,77.381 26.235,75.22 28.39,75.22 28.574,75.405 28.574,75.75 29.047,76.223 ; U6.4@29.047,77.007 29.047,76.223 ; TP113.1@31.852,75.923 29.347,75.923 29.047,76.223
  Bottom Layer w0.152: v1(33.934,64.755) v1(33.934,75.933)
AIN6_N: C37.2 JX3.38 R29.1 TP115.1 U8.5 | length 50.3
  Top Layer w0.152: JX3.38@37.435,65.755 v1(39.649,65.755)
  Top Layer w0.203: TP115.1@31.852,94.738 v1(39.649,94.738)
  Top Layer w0.254: R29.1@23.341,92.874 23.926,92.874 24.075,93.023 24.075,93.378 26.138,95.441 28.39,95.441 28.575,95.256 C37.2@28.574,94.911 29.048,94.439 ; U8.5@29.047,93.654 29.048,94.439 ; TP115.1@31.852,94.738 29.347,94.738 29.048,94.439
  Bottom Layer w0.152: v1(39.649,65.755) v1(39.649,94.738)
AIN6_P: C45.2 JX3.39 R29.4 TP117.1 U8.4 | length 42.4
  Top Layer w0.152: JX3.39@37.435,66.255 v1(39.089,66.255)
  Top Layer w0.203: TP117.1@31.852,88.471 v1@39.089,88.471
  Top Layer w0.254: R29.4@23.341,90.334 23.926,90.334 24.075,90.186 24.075,89.928 26.235,87.768 28.39,87.768 28.574,87.953 28.574,88.297 29.047,88.77 ; U8.4@29.047,89.554 29.047,88.77 ; TP117.1@31.852,88.471 29.347,88.471 29.047,88.77
  Bottom Layer w0.152: v1(39.089,66.255) v1(39.089,88.48)
AIN7_N: C49.2 JX3.41 R31.1 TP119.1 U10.5 | length 56.9
  Top Layer w0.152: v1(35.56,67.255) JX3.41@37.435,67.255
  Top Layer w0.203: TP119.1@31.852,107.235 v1@35.56,107.235
  Top Layer w0.254: R31.1@23.341,105.371 23.926,105.371 24.075,105.52 24.075,105.875 26.138,107.938 28.39,107.938 28.575,107.753 C49.2@28.574,107.408 29.048,106.935 ; U10.5@29.047,106.151 29.048,106.935 ; TP119.1@31.852,107.235 29.347,107.235 29.048,106.935
  Bottom Layer w0.152: v1(35.56,67.255) v1(35.56,107.251)
AIN7_P: C55.2 JX3.42 R31.4 TP121.1 U10.4 | length 50.1
  Top Layer w0.152: v1(35.001,67.755) JX3.42@37.435,67.755
  Top Layer w0.203: TP121.1@31.852,100.967 v1@35.001,100.967
  Top Layer w0.254: R31.4@23.341,102.831 23.926,102.831 24.075,102.682 24.075,102.425 26.235,100.265 28.39,100.265 28.574,100.449 C55.2@28.574,100.794 29.047,101.267 ; U10.4@29.047,102.051 29.047,101.267 ; TP121.1@31.852,100.967 29.347,100.967 29.047,101.267
  Bottom Layer w0.152: v1(35.001,67.755) v1(35.001,100.977)
BB_nFLT: JX2.31 R43.1 | length 99
  Top Layer w0.152: JX2.31@116.28,34.6 v1(116.282,37.299) ; v1(121.551,129.215) R43.1@121.551,129.821
  Bottom Layer w0.152: v1(116.282,37.299) 116.282,40.648 123.45,47.817 123.45,123.125 121.551,125.024 v1(121.551,129.215)
BB_RDY: JX2.28 U12.3 | length 94.1
  Top Layer w0.152: v2(74.25,109.25) U12.3@74.25,111.85 ; JX2.28@114.706,34.393 JX2.28@114.752,34.348 ; JX2.28@114.78,34.6 v1(114.78,36.795)
  Bottom Layer w0.152: v2(74.25,109.25) 74.25,106.475 114.78,65.945 v1(114.78,36.795)
CAN_RX: JX1.177 TP129.1 U17.4 | length 15.5
  Top Layer w0.203: JX1.177@144.28,110.6 144.28,112.28 TP129.1@147.5,115.5 150.05,112.95 153.45,112.95 153.916,113.416 153.916,113.584 153.905,113.595 U17.4@153.905,115.05
CAN_TX: JX1.176 TP128.1 U17.1 | length 16
  Top Layer w0.203: JX1.176@143.78,110.6 143.78,115.78 TP128.1@147.5,119.5 150.095,116.905 U17.1@150.095,115.05
CANH: P10.7 P20.1 U17.7 | length 20
  Top Layer w0.254: P10.7@151.24,130.69 P10.7@151.24,131 ; P10.7@151.39,130.84 151.365,130.815 U17.7@151.365,119.95 151.365,118.085 151.925,117.525 P20.1@158.035,117.525
CANL: P10.2 R36.1 U17.6 | length 15.5
  Top Layer w0.254: P10.2@152.61,128.15 P10.2@152.76,128 152.635,127.875 U17.6@152.635,119.95 152.635,119.09 152.904,118.821 155.24,118.821 155.894,119.475 R36.1@158.58,119.475
DAC0: C14.2 R20.2 R70.4 U1.14 | length 20.2
  Top Layer w0.152: R70.4@29.964,130.34 41.16,130.34 43.124,128.376 U1.14@43.821,128.376 43.808,129.208 41.567,131.381 41.572,131.907 R20.2@41.582,132.923
DAC1: C12.2 R16.2 R70.3 U1.8 | length 24.9
  Top Layer w0.152: R70.3@29.964,129.794 40.73,129.794 43.248,127.276 47.376,127.276 47.698,127.598 47.698,128.353 U1.8@47.721,128.376 47.749,128.404 47.749,129.149 49.414,130.814 v1(49.414,131.193) 49.414,132.91 R16.2@49.421,132.918
DAC2: C10.2 R9.2 R70.2 U1.7 | length 25.6
  Top Layer w0.152: R70.2@29.964,129.29 40.238,129.29 43.328,126.2 44.8,126.2 47.721,123.279 U1.7@47.721,122.476 47.721,121.725 49.488,119.959 C10.2@49.488,119.665 49.488,118.674 R9.2@49.463,118.649
DAC3: C5.2 R5.2 R70.1 U1.1 | length 22.3
  Top Layer w0.152: R70.1@29.964,128.74 39.76,128.74 43.821,124.679 U1.1@43.821,122.476 43.821,121.694 42.112,119.985 R5.2@42.112,118.649
DAC-0: P9.4 R70.5 TP104.1 | length 21.9
  Top Layer w0.203: P9.4@22,135 26.66,130.34 R70.5@28.964,130.34
  Bottom Layer w0.25: TP104.1@22,122 P9.4@22,135
DAC-1: P9.3 R70.6 TP103.1 | length 25.6
  Top Layer w0.203: P9.3@18.5,135 23.71,129.79 R70.6@28.964,129.79
  Bottom Layer w0.25: TP103.1@18.5,122 P9.3@18.5,135
DAC-2: P9.2 R70.7 TP102.1 | length 29.3
  Top Layer w0.203: P9.2@15,135 20.71,129.29 R70.7@28.964,129.29
  Bottom Layer w0.25: TP102.1@15,122 P9.2@15,135
DAC-3: P9.1 R70.8 TP101.1 | length 33.1
  Top Layer w0.203: P9.1@11.5,135 17.76,128.74 R70.8@28.964,128.74
  Bottom Layer w0.203: TP101.1@11.32,122 TP101.1@11.334,122.014
  Bottom Layer w0.25: TP101.1@11.5,122 P9.1@11.5,135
